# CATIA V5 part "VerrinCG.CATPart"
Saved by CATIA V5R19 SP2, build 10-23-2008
Part number: VerrinCG
Bounding box of the stored display mesh (mm): x -61.008 to -31.073, y 158.849 to 228.849, z 159.215 to 183.212
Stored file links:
  D:\France\IFMA\IAO\Projet\VerrinCG.CATPart
  D:\France\IFMA\IAO\Projet\pruangdaja_CAO.CATProduct
  D:\France\IFMA\IAO\Projet\SqueletteVerin.CATPart
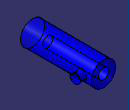
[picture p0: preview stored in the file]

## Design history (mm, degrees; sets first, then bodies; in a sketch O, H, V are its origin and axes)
Body1 (main body)
Body2
  Solid1: linked copy from another document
